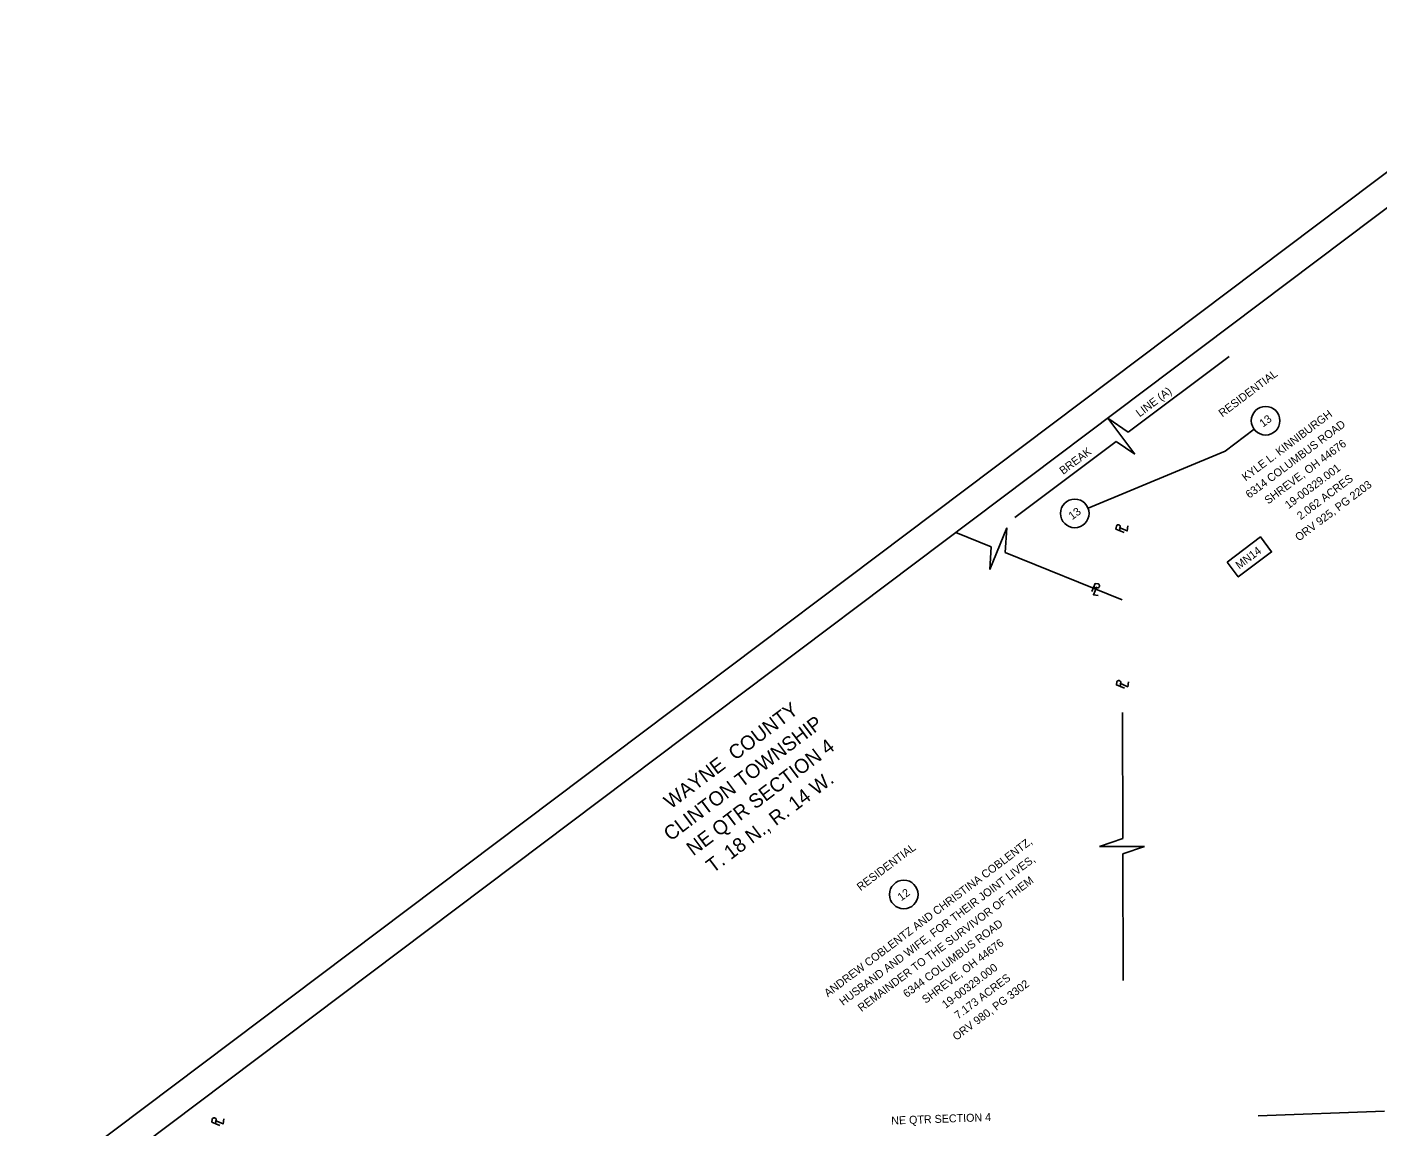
# Model space of a CAD drawing. Extents: x 120947 to 121755, y 462235 to 462996.
# Drawn here: x 120946.8 to 121419.5, y 462610.6 to 462995.5 of the extents above; entities that cross this region are included whole.
import ezdxf

# ---------------------------------------------------------------- set-up
doc = ezdxf.new("R2010")
doc.units = 0
for name, color, linetype in [('DV_X_Property_Line', 7, 'Continuous'), ('DV_X_Section_VMS_Line', 7, 'Continuous'), ('RW_X_Esmt_SH', 7, 'Continuous'), ('SV_P_Control_Cells_Set', 7, 'Continuous'), ('SV_X_Mon_Cells_Found', 7, 'Continuous')]:
    doc.layers.add(name, color=color, linetype=linetype)

msp = doc.modelspace()

# ---------------------------------------------------------------- linework, layer by layer
at = {"layer": 'DV_X_Section_VMS_Line'}
msp.add_lwpolyline([(120976.79, 462596.52), (121488.03, 462981.53), (121740.69, 462646.03), (121229.45, 462261.02)], close=True, dxfattribs=at)
at = {"layer": 'RW_X_Esmt_SH'}
for p, q in [((121329.13, 462819.29), (121329.31, 462820.58)), ((121329.86, 462820), (121329.86, 462820)), ((121320.01, 462799.49), (121321.3, 462799.31)), ((121320.72, 462798.76), (121320.72, 462798.76)), ((121329.32, 462764.74), (121329.5, 462766.03)), ((121330.05, 462765.45), (121330.05, 462765.45)), ((121012.8, 462611.74), (121012.98, 462613.02)), ((121013.53, 462612.44), (121013.53, 462612.44))]:
    msp.add_line(p, q, dxfattribs=at)
for points in [[(121330.65, 462818.66), (121327.82, 462819.84), (121327.97, 462820.87)], [(121328.95, 462820.4), (121331.76, 462819.2), (121332.01, 462820.93)], [(121319.37, 462797.97), (121320.56, 462800.8), (121321.59, 462800.65)], [(121321.12, 462799.67), (121319.92, 462796.86), (121321.65, 462796.61)], [(121330.84, 462764.11), (121328.01, 462765.29), (121328.16, 462766.32)], [(121329.14, 462765.85), (121331.95, 462764.65), (121332.2, 462766.38)], [(121014.32, 462611.1), (121011.49, 462612.29), (121011.64, 462613.31)], [(121012.61, 462612.84), (121015.43, 462611.65), (121015.68, 462613.37)]]:
    msp.add_lwpolyline(points, dxfattribs=at)
for centre, start, end in [((121328.63, 462820.67), 352.4541, 163.3112), ((121321.39, 462799.99), 262.4541, 73.3112), ((121328.82, 462766.12), 352.4541, 163.3112), ((121012.3, 462613.11), 352.4541, 163.3112)]:
    msp.add_arc(centre, 0.69, start, end, dxfattribs=at)
at = {"layer": 'SV_P_Control_Cells_Set'}
msp.add_lwpolyline([(121211.5, 462234.99), (121754.7, 462644.06), (121490, 462995.54), (120946.81, 462586.46)], close=True, dxfattribs=at)
at = {"layer": 'SV_X_Mon_Cells_Found'}
for p, q in [((121367.39, 462880.25), (121332.15, 462853.71)), ((121334.49, 462846.02), (121325.01, 462858.6)), ((121332.15, 462853.71), (121325.01, 462858.6)), ((121327.86, 462850.49), (121292.5, 462823.85)), ((121334.49, 462846.02), (121327.86, 462850.49)), ((121283.68, 462805.67), (121289.62, 462820.26)), ((121289.08, 462811.63), (121289.62, 462820.26)), ((121284.11, 462813.65), (121271.77, 462818.67)), ((121283.68, 462805.67), (121284.11, 462813.65)), ((121329.95, 462795.01), (121289.08, 462811.63)), ((121330.08, 462755.61), (121330.24, 462711.5)), ((121330.24, 462711.5), (121322.05, 462708.71)), ((121337.8, 462708.77), (121322.05, 462708.71)), ((121337.8, 462708.77), (121330.25, 462706.13)), ((121330.25, 462706.13), (121330.41, 462661.86)), ((121421.79, 462616.06), (121377.55, 462614.49))]:
    msp.add_line(p, q, dxfattribs=at)
msp.add_lwpolyline([(121376.19, 462854.74), (121366.05, 462847.1), (121318.1, 462827.1)], dxfattribs=at)
msp.add_lwpolyline([(121366.72, 462808.3), (121378.36, 462817.07), (121382.29, 462811.85), (121370.65, 462803.09)], close=True, dxfattribs=at)
for centre in [(121380.19, 462857.74), (121313.42, 462825.32), (121253.6, 462691.94)]:
    msp.add_circle(centre, 5, dxfattribs=at)

# ---------------------------------------------------------------- texts
at = {"layer": 'DV_X_Property_Line'}
for s, p in [('               WAYNE  COUNTY              ', (121149.79, 462704.9)), ('             CLINTON TOWNSHIP             ', (121152.67, 462695.88)), ('             NE QTR SECTION 4             ', (121160.66, 462690.72)), ('            T. 18 N., R. 14 W.            ', (121169.02, 462685.83))]:
    msp.add_text(s, height=5, rotation=36.9831, dxfattribs=at).set_placement(p)
at = {"layer": 'SV_X_Mon_Cells_Found'}
for s, rotation, p in [('RESIDENTIAL', 36.9831, (121365.07, 462858.88)), ('BREAK                    LINE (A)', 36.9831, (121309.37, 462838.75)), ('KYLE L. KINNIBURGH', 36.9831, (121373.22, 462836.48)), ('6314 COLUMBUS ROAD', 36.9831, (121374.5, 462830.43)), ('13', 36.9831, (121379.31, 462855.33)), ('SHREVE, OH 44676', 36.9831, (121381.1, 462828.39)), ('19-00329.001', 36.9831, (121388.24, 462826.76)), ('2.062 ACRES', 36.9831, (121392.46, 462822.92)), ('ORV 925, PG 2203', 36.9831, (121391.83, 462815.43)), ('13', 36.9831, (121312.54, 462822.91)), ('MN14', 36.9831, (121370.99, 462805.67)), ('ANDREW COBLENTZ AND CHRISTINA COBLENTZ,', 36.9831, (121227.04, 462655.92)), ('RESIDENTIAL', 36.9831, (121238.48, 462693.07)), ('HUSBAND AND WIFE, FOR THEIR JOINT LIVES,', 36.9831, (121232.35, 462652.91)), ('REMAINDER TO THE SURVIVOR OF THEM', 36.9831, (121238.8, 462650.75)), ('12', 36.9831, (121252.71, 462689.52)), ('6344 COLUMBUS ROAD', 36.9831, (121254.65, 462655.68)), ('SHREVE, OH 44676', 36.9831, (121261.25, 462653.64)), ('19-00329.000', 36.9831, (121268.24, 462651.89)), ('7.173 ACRES', 36.9831, (121272.61, 462648.17)), ('ORV 980, PG 3302', 36.9831, (121271.97, 462640.68)), ('NE QTR SECTION 4', 2.0355, (121249.25, 462611.42))]:
    msp.add_text(s, height=2.8, rotation=rotation, dxfattribs=at).set_placement(p)

doc.saveas('drawing.dxf')
